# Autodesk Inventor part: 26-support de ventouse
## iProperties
Created: 2011-02
Part Number: 26-support de ventouse
Document SubType Name: Modeling
Designer: eric
Density: 1 g/cm^3
Author: eric
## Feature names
1. Base1
